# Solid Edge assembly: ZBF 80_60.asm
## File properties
Title: Zylinder
Author: bmolnar
Template: iso metric assembly.asm
Last saved by: bmolnar
Revision: 13
Application: Solid Edge
Username: bmolnar
Dokumentum tartalom típus: 1
Document Number: ZBF 80/60
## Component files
Profilrohr.par
Kolbenstange.par
Mutter.par
Kit.par
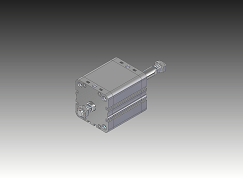
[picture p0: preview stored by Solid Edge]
